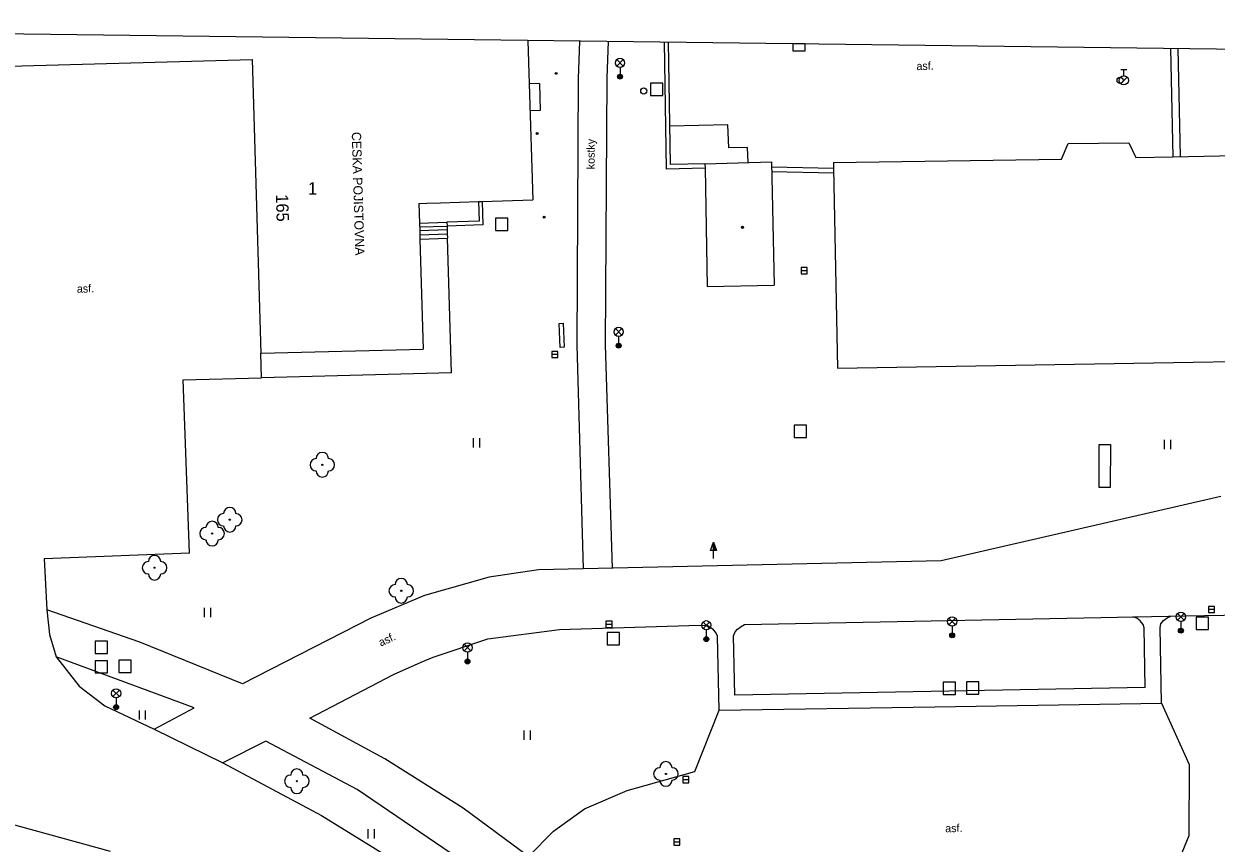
# Model space of a CAD drawing. Extents: x -641829 to -641525, y -1114855 to -1114359.
# Drawn here: x -641760.1 to -641663.2, y -1114425.4 to -1114358.9 of the extents above; entities that cross this region are included whole.
import ezdxf

# ---------------------------------------------------------------- set-up
doc = ezdxf.new("R2010")
doc.units = 0
for name, color, linetype in [('Vrstva 1', 7, 'Continuous'), ('Vrstva 10', 7, 'Continuous'), ('Vrstva 11', 7, 'Continuous'), ('Vrstva 20', 7, 'Continuous'), ('Vrstva 22', 7, 'Continuous'), ('Vrstva 24', 7, 'Continuous'), ('Vrstva 25', 7, 'Continuous'), ('Vrstva 26', 7, 'Continuous'), ('Vrstva 27', 7, 'Continuous'), ('Vrstva 28', 7, 'Continuous'), ('Vrstva 33', 7, 'Continuous'), ('Vrstva 36', 7, 'Continuous'), ('Vrstva 39', 7, 'Continuous'), ('Vrstva 40', 7, 'Continuous'), ('Vrstva 41', 7, 'Continuous'), ('Vrstva 46', 7, 'Continuous'), ('Vrstva 47', 7, 'Continuous'), ('Vrstva 5', 7, 'Continuous'), ('Vrstva 6', 7, 'Continuous'), ('Vrstva 7', 7, 'Continuous')]:
    doc.layers.add(name, color=color, linetype=linetype)

msp = doc.modelspace()

# ---------------------------------------------------------------- linework, layer by layer
at = {"layer": 'Vrstva 1'}
msp.add_line((-641525.3, -1114362.64), (-641828.67, -1114358.89), dxfattribs=at)
at = {"layer": 'Vrstva 10'}
for p, q in [((-641740.8, -1114387.64), (-641740.85, -1114385.64)), ((-641747.16, -1114387.8), (-641740.8, -1114387.64)), ((-641746.63, -1114401.89), (-641747.16, -1114387.8)), ((-641746.63, -1114401.89), (-641758.44, -1114402.33)), ((-641758.44, -1114402.33), (-641758.23, -1114406.47)), ((-641758.23, -1114406.47), (-641758, -1114408.48)), ((-641758, -1114408.48), (-641757.48, -1114410.31)), ((-641757.48, -1114410.31), (-641755.6, -1114412.69)), ((-641755.6, -1114412.69), (-641753.51, -1114414.28)), ((-641753.51, -1114414.28), (-641749.51, -1114416.17)), ((-641686.1, -1114414.37), (-641667.68, -1114414.07)), ((-641667.68, -1114414.07), (-641665.43, -1114419.05)), ((-641705.6, -1114419.62), (-641703.62, -1114414.62)), ((-641703.62, -1114414.62), (-641686.1, -1114414.37)), ((-641749.51, -1114416.17), (-641743.94, -1114418.91)), ((-641781.57, -1114418.24), (-641753.07, -1114426.08)), ((-641743.94, -1114418.91), (-641735.93, -1114423.19)), ((-641665.43, -1114419.05), (-641665.47, -1114424.84)), ((-641711.1, -1114421.15), (-641705.6, -1114419.62)), ((-641714.56, -1114422.63), (-641711.1, -1114421.15)), ((-641717.06, -1114424.45), (-641714.56, -1114422.63)), ((-641735.93, -1114423.19), (-641730.26, -1114426.67)), ((-641719.11, -1114426.51), (-641717.06, -1114424.45)), ((-641665.47, -1114424.84), (-641667.56, -1114429.94))]:
    msp.add_line(p, q, dxfattribs=at)
at = {"layer": 'Vrstva 11'}
for p, q in [((-641715.05, -1114363.36), (-641714.938, -1114360.296)), ((-641712.72, -1114363.27), (-641712.604, -1114360.325)), ((-641718.22, -1114363.73), (-641719.05, -1114363.76)), ((-641718.22, -1114363.73), (-641718.15, -1114365.92)), ((-641715.15, -1114384.99), (-641715.05, -1114363.36)), ((-641712.84, -1114384.96), (-641712.72, -1114363.27)), ((-641718.15, -1114365.92), (-641718.98, -1114365.95)), ((-641702.9, -1114367.08), (-641707.62, -1114367.2)), ((-641702.84, -1114368.96), (-641702.9, -1114367.08)), ((-641701.32, -1114368.92), (-641702.84, -1114368.96)), ((-641701.26, -1114370.15), (-641701.32, -1114368.92)), ((-641723.16, -1114373.33), (-641723.11, -1114374.92)), ((-641722.86, -1114373.32), (-641722.8, -1114375.22)), ((-641727.96, -1114375.07), (-641725.73, -1114375)), ((-641727.95, -1114375.37), (-641725.72, -1114375.31)), ((-641723.11, -1114374.92), (-641725.73, -1114375)), ((-641725.73, -1114375), (-641725.72, -1114375.31)), ((-641722.8, -1114375.22), (-641725.72, -1114375.31)), ((-641725.72, -1114375.31), (-641725.7, -1114375.95)), ((-641727.94, -1114375.67), (-641725.71, -1114375.6)), ((-641727.93, -1114376.02), (-641725.7, -1114375.95)), ((-641727.92, -1114376.37), (-641725.69, -1114376.3)), ((-641725.7, -1114375.95), (-641725.69, -1114376.3)), ((-641725.36, -1114387.24), (-641725.69, -1114376.3)), ((-641714.63, -1114403.15), (-641715.15, -1114384.99)), ((-641712.28, -1114403.09), (-641712.84, -1114384.96)), ((-641725.36, -1114387.24), (-641740.8, -1114387.64)), ((-641662.86, -1114397.27), (-641685.59, -1114402.49)), ((-641685.59, -1114402.49), (-641718.28, -1114403.23)), ((-641718.28, -1114403.23), (-641722.31, -1114403.83)), ((-641722.31, -1114403.83), (-641727.55, -1114405.33)), ((-641727.55, -1114405.33), (-641731.9, -1114407.15)), ((-641750.67, -1114409.11), (-641758.23, -1114406.47)), ((-641731.9, -1114407.15), (-641742.34, -1114412.5)), ((-641701.56, -1114407.67), (-641665.75, -1114406.97)), ((-641669.7, -1114407.17), (-641670.02, -1114407.05)), ((-641669.43, -1114407.37), (-641669.7, -1114407.17)), ((-641669.17, -1114407.67), (-641669.43, -1114407.37)), ((-641667.73, -1114407.62), (-641667.53, -1114407.36)), ((-641667.53, -1114407.36), (-641667.24, -1114407.14)), ((-641667.24, -1114407.14), (-641666.92, -1114406.99)), ((-641665.75, -1114406.97), (-641646.17, -1114406.59)), ((-641722.41, -1114408.83), (-641716.58, -1114408.09)), ((-641716.58, -1114408.09), (-641706.08, -1114407.76)), ((-641706.08, -1114407.76), (-641704.65, -1114407.73)), ((-641704.37, -1114407.89), (-641704.65, -1114407.73)), ((-641704.08, -1114408.1), (-641704.37, -1114407.89)), ((-641703.89, -1114408.31), (-641704.08, -1114408.1)), ((-641703.74, -1114408.61), (-641703.89, -1114408.31)), ((-641702.44, -1114408.59), (-641702.32, -1114408.27)), ((-641702.32, -1114408.27), (-641702.12, -1114408.04)), ((-641702.12, -1114408.04), (-641701.84, -1114407.83)), ((-641701.84, -1114407.83), (-641701.56, -1114407.67)), ((-641669.1, -1114407.94), (-641669.17, -1114407.67)), ((-641669, -1114412.8), (-641669.1, -1114407.94)), ((-641667.8, -1114407.91), (-641667.73, -1114407.62)), ((-641667.68, -1114414.07), (-641667.8, -1114407.91)), ((-641742.34, -1114412.5), (-641750.67, -1114409.11)), ((-641726.85, -1114410.32), (-641722.41, -1114408.83)), ((-641703.62, -1114414.62), (-641703.74, -1114408.61)), ((-641702.34, -1114413.4), (-641702.44, -1114408.59)), ((-641746.26, -1114414.45), (-641757.48, -1114410.31)), ((-641727.82, -1114410.72), (-641726.85, -1114410.32)), ((-641730.06, -1114411.74), (-641727.82, -1114410.72)), ((-641736.86, -1114415.29), (-641730.06, -1114411.74)), ((-641669, -1114412.8), (-641702.34, -1114413.4)), ((-641749.51, -1114416.17), (-641746.26, -1114414.45)), ((-641730.76, -1114418.58), (-641736.86, -1114415.29)), ((-641740.43, -1114417.14), (-641743.94, -1114418.91)), ((-641733.03, -1114421.08), (-641740.43, -1114417.14)), ((-641724.4, -1114422.58), (-641730.76, -1114418.58)), ((-641721.35, -1114428.99), (-641733.03, -1114421.08)), ((-641719.11, -1114426.51), (-641724.4, -1114422.58))]:
    msp.add_line(p, q, dxfattribs=at)
at = {"layer": 'Vrstva 20'}
for centre, radius in [((-641716.86, -1114362.91), 0.075), ((-641716.86, -1114362.91), 0.0204), ((-641718.4, -1114367.8), 0.075), ((-641718.4, -1114367.8), 0.0204), ((-641717.84, -1114374.59), 0.075), ((-641717.84, -1114374.59), 0.0204)]:
    msp.add_circle(centre, radius, dxfattribs=at)
at = {"layer": 'Vrstva 22'}
for centre in [(-641735.85, -1114394.7), (-641743.37, -1114399.16), (-641744.8, -1114400.29), (-641749.48, -1114403.06), (-641729.44, -1114404.93), (-641707.94, -1114419.81), (-641737.92, -1114420.4)]:
    msp.add_circle(centre, 0.05, dxfattribs=at)
for centre, start, end in [((-641735.85, -1114394.2), 0, 180), ((-641736.35, -1114394.7), 90, 270), ((-641735.35, -1114394.7), 270, 90), ((-641735.85, -1114395.2), 180, 0), ((-641743.87, -1114399.16), 90, 270), ((-641743.37, -1114398.66), 0, 180), ((-641742.87, -1114399.16), 270, 90), ((-641744.8, -1114399.79), 0, 180), ((-641743.37, -1114399.66), 180, 0), ((-641745.3, -1114400.29), 90, 270), ((-641744.3, -1114400.29), 270, 90), ((-641744.8, -1114400.79), 180, 0), ((-641749.98, -1114403.06), 90, 270), ((-641749.48, -1114402.56), 0, 180), ((-641748.98, -1114403.06), 270, 90), ((-641749.48, -1114403.56), 180, 0), ((-641729.94, -1114404.93), 90, 270), ((-641729.44, -1114404.43), 0, 180), ((-641728.94, -1114404.93), 270, 90), ((-641729.44, -1114405.43), 180, 0), ((-641707.94, -1114419.31), 0, 180), ((-641738.42, -1114420.4), 90, 270), ((-641737.92, -1114419.9), 0, 180), ((-641737.42, -1114420.4), 270, 90), ((-641708.44, -1114419.81), 90, 270), ((-641707.44, -1114419.81), 270, 90), ((-641737.92, -1114420.9), 180, 0), ((-641707.94, -1114420.31), 180, 0)]:
    msp.add_arc(centre, 0.5, start, end, dxfattribs=at)
at = {"layer": 'Vrstva 24'}
for points in [[(-641716.29, -1114383.21), (-641716.2, -1114385.16), (-641716.52, -1114385.18), (-641716.61, -1114383.23), (-641716.29, -1114383.21)], [(-641672.76, -1114396.54), (-641672.74, -1114393.04), (-641671.84, -1114393.05), (-641671.86, -1114396.55), (-641672.76, -1114396.54)]]:
    msp.add_lwpolyline(points, dxfattribs=at)
at = {"layer": 'Vrstva 25'}
for p, q in [((-641704.322, -1114401.668), (-641704.07, -1114400.994)), ((-641704.07, -1114401.668), (-641704.322, -1114401.668)), ((-641704.07, -1114402.32), (-641704.07, -1114401.67))]:
    msp.add_line(p, q, dxfattribs=at)
for points in [[(-641703.82, -1114401.67), (-641704.07, -1114401.67), (-641704.07, -1114400.994), (-641704.07, -1114400.994)], [(-641703.878, -1114401.63), (-641704.03, -1114401.63), (-641704.03, -1114401.216)], [(-641703.934, -1114401.59), (-641703.99, -1114401.59), (-641703.99, -1114401.44)]]:
    msp.add_lwpolyline(points, close=True, dxfattribs=at)
at = {"layer": 'Vrstva 26'}
for p, q in [((-641696.63, -1114360.522), (-641697.63, -1114360.51)), ((-641697.63, -1114360.51), (-641697.63, -1114361.07)), ((-641696.63, -1114361.07), (-641696.63, -1114360.522)), ((-641697.63, -1114361.07), (-641696.63, -1114361.07))]:
    msp.add_line(p, q, dxfattribs=at)
for points in [[(-641708.18, -1114363.7), (-641709.18, -1114363.7), (-641709.18, -1114364.7), (-641708.18, -1114364.7)], [(-641720.79, -1114374.67), (-641721.79, -1114374.67), (-641721.79, -1114375.67), (-641720.79, -1114375.67)], [(-641696.52, -1114391.49), (-641697.52, -1114391.49), (-641697.52, -1114392.49), (-641696.52, -1114392.49)], [(-641663.86, -1114407.08), (-641664.86, -1114407.08), (-641664.86, -1114408.08), (-641663.86, -1114408.08)], [(-641711.7, -1114408.32), (-641712.7, -1114408.32), (-641712.7, -1114409.32), (-641711.7, -1114409.32)], [(-641753.31, -1114409.02), (-641754.31, -1114409.02), (-641754.31, -1114410.02), (-641753.31, -1114410.02)], [(-641753.3, -1114410.61), (-641754.3, -1114410.61), (-641754.3, -1114411.61), (-641753.3, -1114411.61)], [(-641751.38, -1114410.57), (-641752.38, -1114410.57), (-641752.38, -1114411.57), (-641751.38, -1114411.57)], [(-641684.42, -1114412.35), (-641685.42, -1114412.35), (-641685.42, -1114413.35), (-641684.42, -1114413.35)], [(-641682.53, -1114412.33), (-641683.53, -1114412.33), (-641683.53, -1114413.33), (-641682.53, -1114413.33)]]:
    msp.add_lwpolyline(points, close=True, dxfattribs=at)
at = {"layer": 'Vrstva 27'}
for p, q in [((-641696.46, -1114378.94), (-641696.96, -1114378.94)), ((-641716.72, -1114385.74), (-641717.22, -1114385.74)), ((-641663.37, -1114406.46), (-641663.87, -1114406.46)), ((-641712.32, -1114407.66), (-641712.82, -1114407.66)), ((-641706.08, -1114420.28), (-641706.58, -1114420.28)), ((-641706.8, -1114425.34), (-641707.3, -1114425.34))]:
    msp.add_line(p, q, dxfattribs=at)
for points in [[(-641696.46, -1114378.69), (-641696.96, -1114378.69), (-641696.96, -1114379.19), (-641696.46, -1114379.19)], [(-641716.72, -1114385.49), (-641717.22, -1114385.49), (-641717.22, -1114385.99), (-641716.72, -1114385.99)], [(-641663.37, -1114406.21), (-641663.87, -1114406.21), (-641663.87, -1114406.71), (-641663.37, -1114406.71)], [(-641712.32, -1114407.41), (-641712.82, -1114407.41), (-641712.82, -1114407.91), (-641712.32, -1114407.91)], [(-641706.08, -1114420.03), (-641706.58, -1114420.03), (-641706.58, -1114420.53), (-641706.08, -1114420.53)], [(-641706.8, -1114425.09), (-641707.3, -1114425.09), (-641707.3, -1114425.59), (-641706.8, -1114425.59)]]:
    msp.add_lwpolyline(points, close=True, dxfattribs=at)
at = {"layer": 'Vrstva 28'}
for p, q in [((-641671, -1114362.604), (-641670.5, -1114362.604)), ((-641670.75, -1114363.104), (-641670.75, -1114362.604)), ((-641671.008, -1114363.752), (-641670.478, -1114363.222))]:
    msp.add_line(p, q, dxfattribs=at)
for centre, radius in [((-641671.05, -1114363.49), 0.25), ((-641670.75, -1114363.48), 0.375), ((-641709.74, -1114364.34), 0.25)]:
    msp.add_circle(centre, radius, dxfattribs=at)
at = {"layer": 'Vrstva 33'}
for p, q in [((-641711.934, -1114362.32), (-641711.406, -1114361.79)), ((-641711.934, -1114361.79), (-641711.406, -1114362.32)), ((-641711.67, -1114362.43), (-641711.67, -1114363.18)), ((-641712.044, -1114384.17), (-641711.516, -1114383.64)), ((-641712.044, -1114383.64), (-641711.516, -1114384.17)), ((-641711.78, -1114384.28), (-641711.78, -1114385.03)), ((-641704.924, -1114408), (-641704.396, -1114407.47)), ((-641704.924, -1114407.47), (-641704.396, -1114408)), ((-641684.954, -1114407.69), (-641684.426, -1114407.16)), ((-641684.954, -1114407.16), (-641684.426, -1114407.69)), ((-641666.374, -1114407.31), (-641665.846, -1114406.78)), ((-641666.374, -1114406.78), (-641665.846, -1114407.31)), ((-641666.11, -1114407.42), (-641666.11, -1114408.17)), ((-641704.66, -1114408.11), (-641704.66, -1114408.86)), ((-641684.69, -1114407.8), (-641684.69, -1114408.55)), ((-641724.324, -1114409.81), (-641723.796, -1114409.28)), ((-641724.324, -1114409.28), (-641723.796, -1114409.81)), ((-641724.06, -1114409.92), (-641724.06, -1114410.67)), ((-641752.864, -1114413.53), (-641752.336, -1114413)), ((-641752.864, -1114413), (-641752.336, -1114413.53)), ((-641752.6, -1114413.64), (-641752.6, -1114414.39))]:
    msp.add_line(p, q, dxfattribs=at)
for centre, radius in [((-641711.67, -1114362.055), 0.375), ((-641711.67, -1114363.18), 0.2), ((-641711.67, -1114363.18), 0.145), ((-641711.67, -1114363.18), 0.0876), ((-641711.78, -1114383.905), 0.375), ((-641711.78, -1114385.03), 0.2), ((-641711.78, -1114385.03), 0.145), ((-641711.78, -1114385.03), 0.0876), ((-641704.66, -1114407.735), 0.375), ((-641684.69, -1114407.425), 0.375), ((-641666.11, -1114407.045), 0.375), ((-641684.69, -1114408.55), 0.2), ((-641684.69, -1114408.55), 0.145), ((-641684.69, -1114408.55), 0.0876), ((-641666.11, -1114408.17), 0.2), ((-641666.11, -1114408.17), 0.145), ((-641666.11, -1114408.17), 0.0876), ((-641724.06, -1114409.545), 0.375), ((-641704.66, -1114408.86), 0.2), ((-641704.66, -1114408.86), 0.145), ((-641704.66, -1114408.86), 0.0876), ((-641724.06, -1114410.67), 0.2), ((-641724.06, -1114410.67), 0.145), ((-641724.06, -1114410.67), 0.0876), ((-641752.6, -1114413.265), 0.375), ((-641752.6, -1114414.39), 0.2), ((-641752.6, -1114414.39), 0.145), ((-641752.6, -1114414.39), 0.0876)]:
    msp.add_circle(centre, radius, dxfattribs=at)
at = {"layer": 'Vrstva 36'}
for p, q in [((-641723.564, -1114393.292), (-641723.564, -1114392.544)), ((-641723.064, -1114393.292), (-641723.064, -1114392.544)), ((-641667.434, -1114393.434), (-641667.434, -1114392.682)), ((-641666.934, -1114393.434), (-641666.934, -1114392.682)), ((-641745.414, -1114407.074), (-641745.414, -1114406.322)), ((-641744.914, -1114407.074), (-641744.914, -1114406.322)), ((-641750.704, -1114415.392), (-641750.704, -1114414.644)), ((-641750.204, -1114415.392), (-641750.204, -1114414.644)), ((-641719.444, -1114417.044), (-641719.444, -1114416.292)), ((-641718.944, -1114417.044), (-641718.944, -1114416.292)), ((-641732.124, -1114425.052), (-641732.124, -1114424.304)), ((-641731.624, -1114425.052), (-641731.624, -1114424.304))]:
    msp.add_line(p, q, dxfattribs=at)
at = {"layer": 'Vrstva 39'}
for radius in [0.09, 0.0398]:
    msp.add_circle((-641701.72, -1114375.42), radius, dxfattribs=at)
at = {"layer": 'Vrstva 5'}
for p, q in [((-641770.96, -1114362.58), (-641741.54, -1114361.78)), ((-641741.54, -1114361.78), (-641740.85, -1114385.64)), ((-641675.81, -1114369.87), (-641675.28, -1114368.62)), ((-641675.28, -1114368.62), (-641670.35, -1114368.56)), ((-641670.35, -1114368.56), (-641669.77, -1114369.75)), ((-641704.77, -1114370.27), (-641699.36, -1114370.09)), ((-641699.36, -1114370.09), (-641699.16, -1114380.12)), ((-641694.34, -1114370.16), (-641675.81, -1114369.87)), ((-641704.59, -1114380.23), (-641699.16, -1114380.12)), ((-641740.85, -1114385.64), (-641727.65, -1114385.3))]:
    msp.add_line(p, q, dxfattribs=at)
for points in [[(-641719.158, -1114360.244), (-641719.05, -1114363.76), (-641718.76, -1114373.19)], [(-641669.77, -1114369.75), (-641666.76, -1114369.69), (-641632.72, -1114368.96)], [(-641704.77, -1114370.27), (-641704.76, -1114370.62), (-641704.59, -1114380.23)], [(-641694.34, -1114370.16), (-641694.33, -1114370.65), (-641694, -1114386.85)], [(-641728.01, -1114373.48), (-641727.36, -1114373.46), (-641726.26, -1114373.42), (-641723.16, -1114373.33), (-641722.86, -1114373.32), (-641718.76, -1114373.19)], [(-641728.01, -1114373.48), (-641727.96, -1114375.07), (-641727.94, -1114375.67), (-641727.92, -1114376.37), (-641727.65, -1114385.3)], [(-641694, -1114386.85), (-641633, -1114385.83), (-641619.55, -1114385.61)]]:
    msp.add_lwpolyline(points, dxfattribs=at)
at = {"layer": 'Vrstva 6'}
msp.add_line((-641727.36, -1114373.46), (-641726.26, -1114373.42), dxfattribs=at)
at = {"layer": 'Vrstva 7'}
for p, q in [((-641708.071, -1114360.381), (-641707.92, -1114370.68)), ((-641707.57, -1114370.32), (-641707.718, -1114360.385)), ((-641666.96, -1114360.889), (-641666.76, -1114369.69)), ((-641666.36, -1114360.896), (-641666.16, -1114369.67)), ((-641704.76, -1114370.62), (-641707.92, -1114370.68)), ((-641704.77, -1114370.27), (-641707.57, -1114370.32)), ((-641694.33, -1114370.65), (-641699.35, -1114370.52)), ((-641699.34, -1114370.87), (-641694.32, -1114371))]:
    msp.add_line(p, q, dxfattribs=at)

# ---------------------------------------------------------------- texts
at = {"layer": 'Vrstva 40'}
for s, rotation, p in [('asf.', 1.68737, (-641687.58, -1114362.65)), ('kostky', 89.73511, (-641713.73, -1114370.7)), ('asf.', 1.47668, (-641755.78, -1114380.73)), ('asf.', 24.48249, (-641731.1, -1114409.47)), ('asf.', 1.0301, (-641685.25, -1114424.55))]:
    msp.add_text(s, height=0.65, rotation=rotation, dxfattribs=at).set_placement(p)
at = {"layer": 'Vrstva 41'}
msp.add_text('CESKA POJISTOVNA', height=0.75, rotation=271.65906, dxfattribs=at).set_placement((-641733.46, -1114367.68))
at = {"layer": 'Vrstva 46'}
msp.add_text('1', height=1, dxfattribs=at).set_placement((-641737.02, -1114372.75))
at = {"layer": 'Vrstva 47'}
msp.add_text('165', height=1, rotation=271.65906, dxfattribs=at).set_placement((-641739.62, -1114372.74))

doc.saveas('drawing.dxf')
